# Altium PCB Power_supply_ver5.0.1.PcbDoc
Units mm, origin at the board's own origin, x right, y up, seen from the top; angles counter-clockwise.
Board outline 94.86 x 64.25 mm, 2 copper layers (Top Layer, Bottom Layer); 104 components, 45 nets, 301 pads, 37 vias.
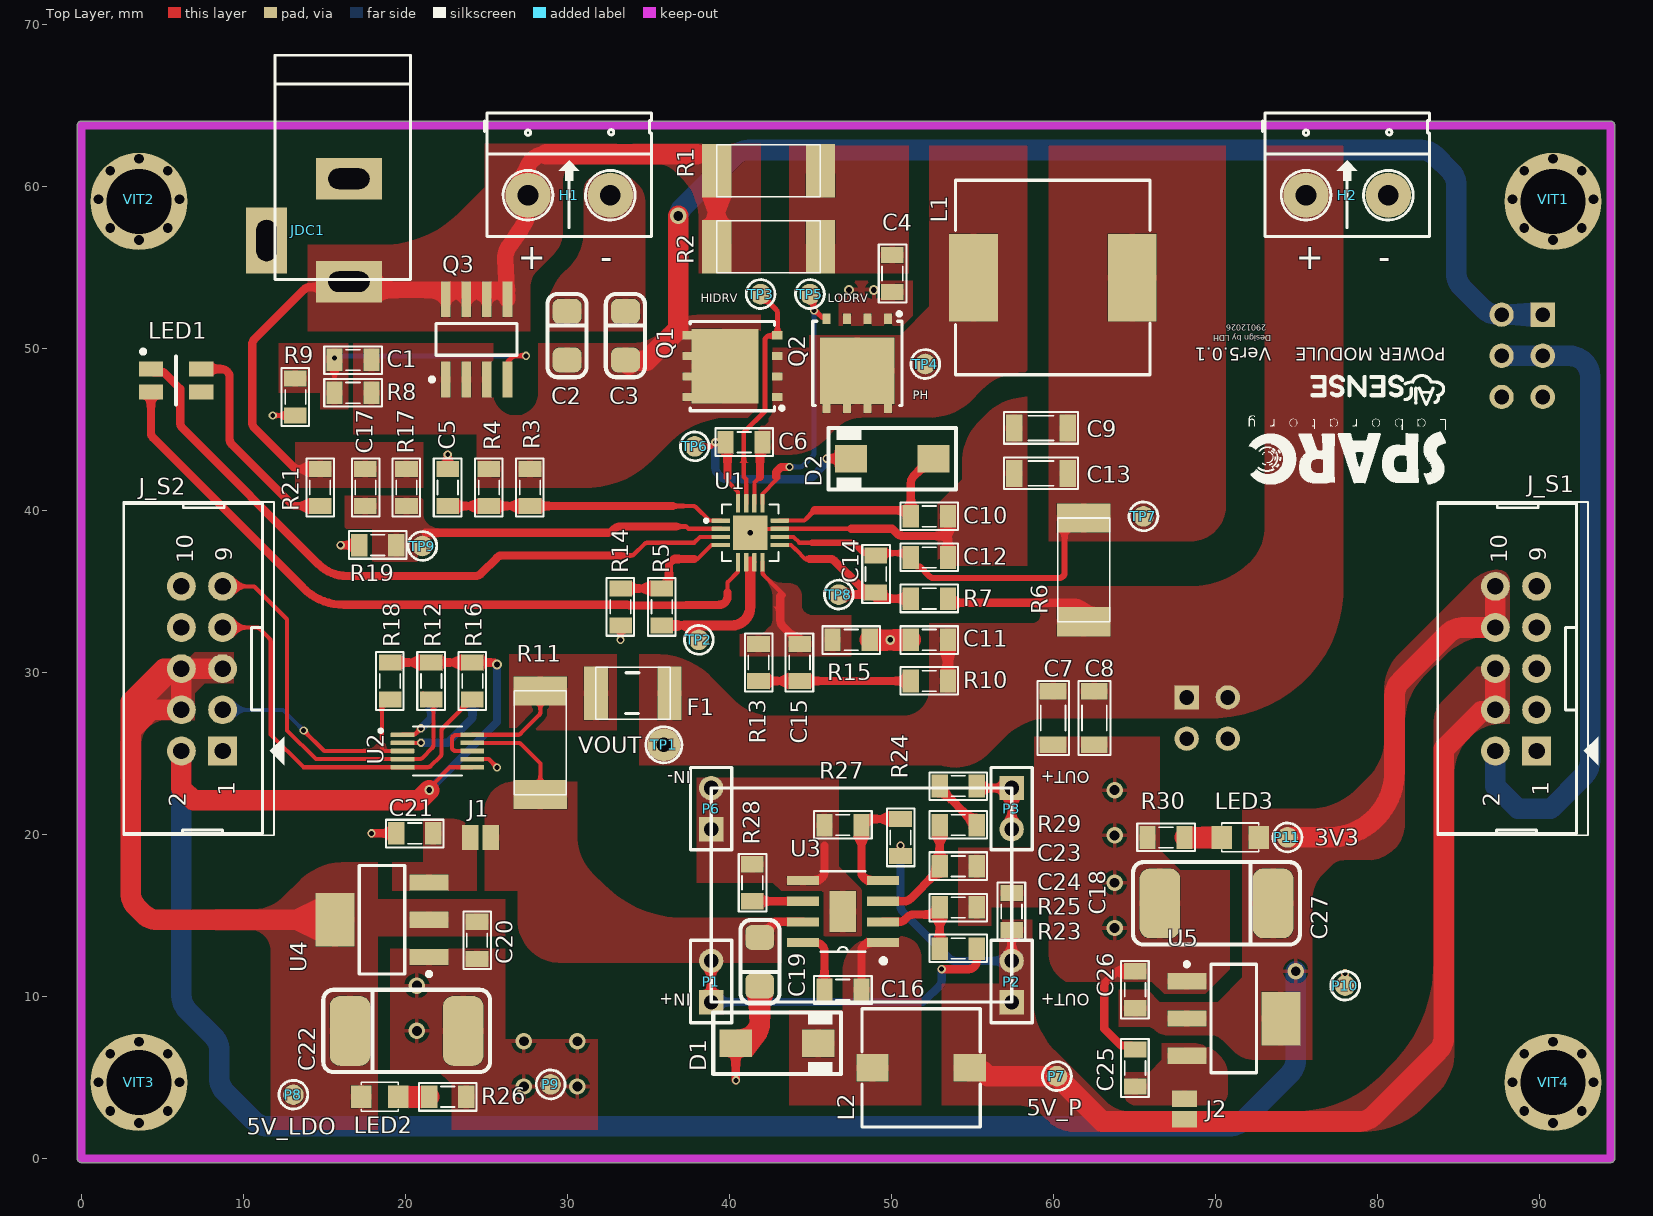
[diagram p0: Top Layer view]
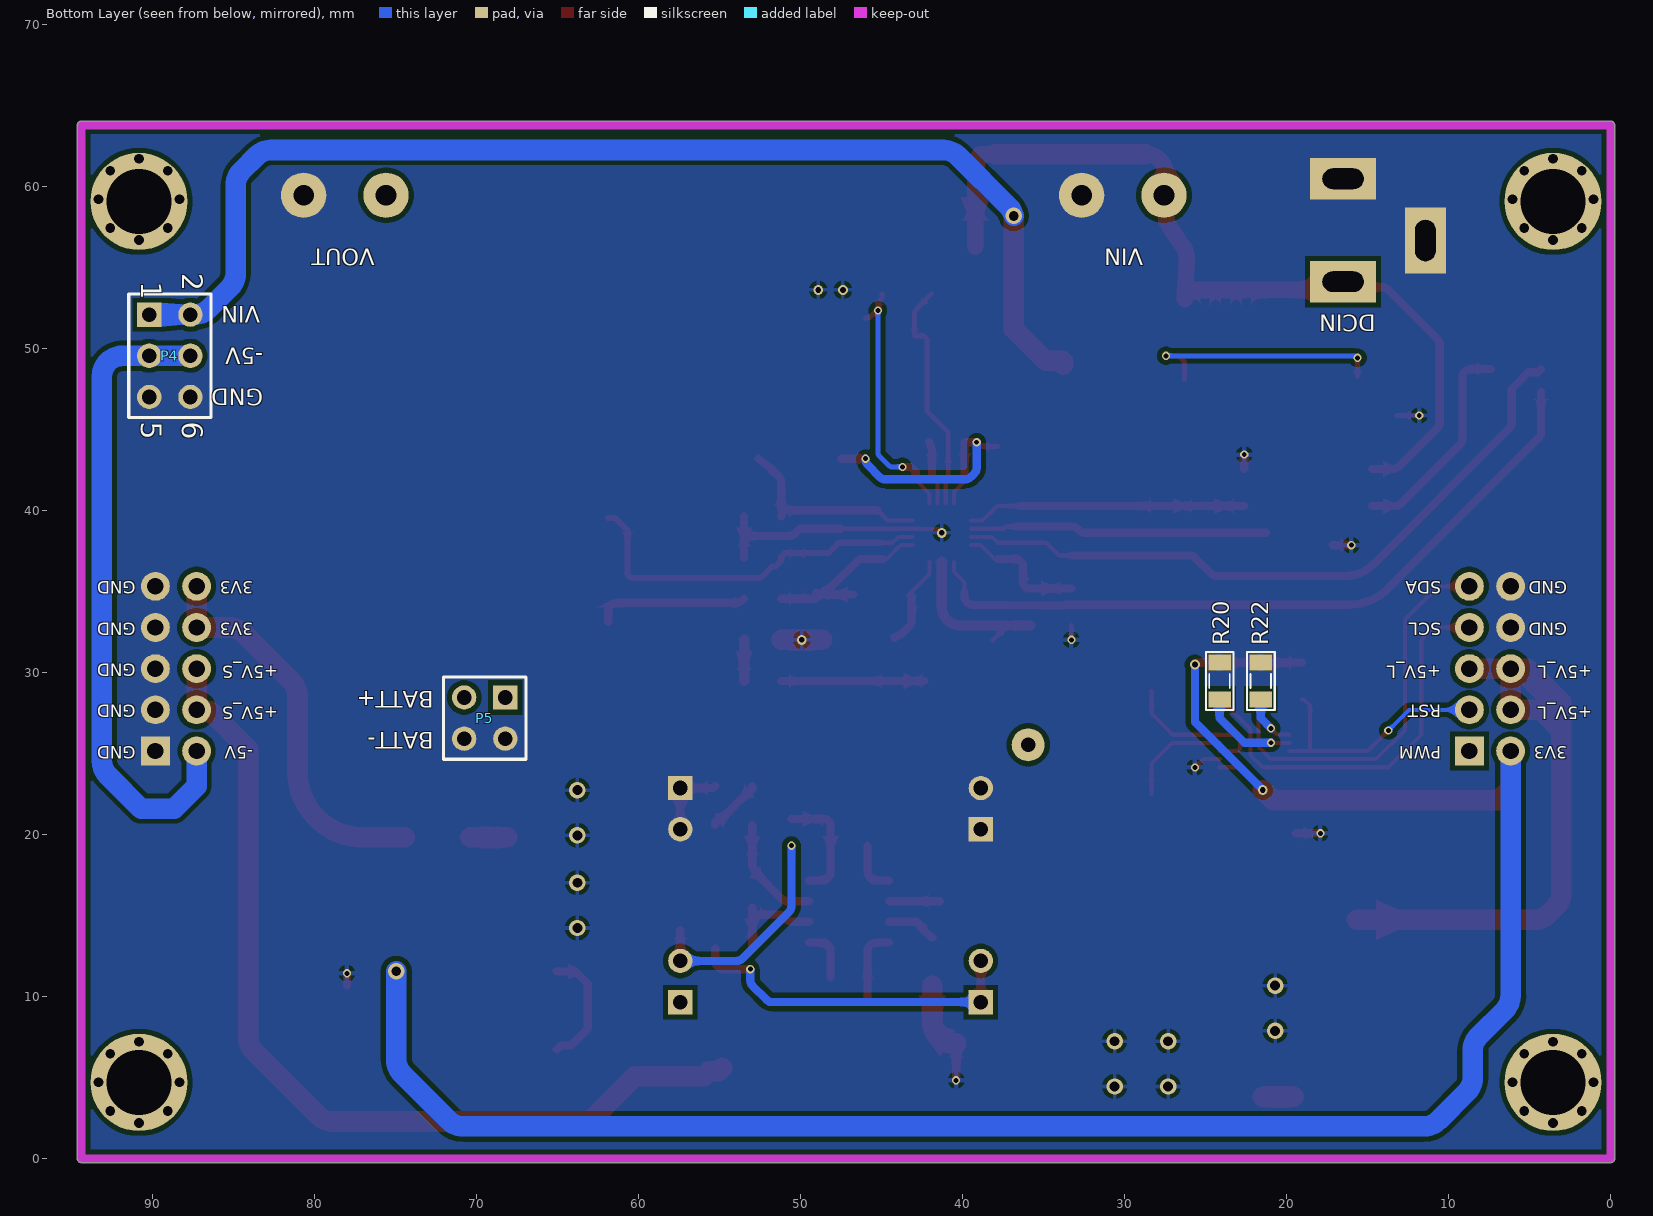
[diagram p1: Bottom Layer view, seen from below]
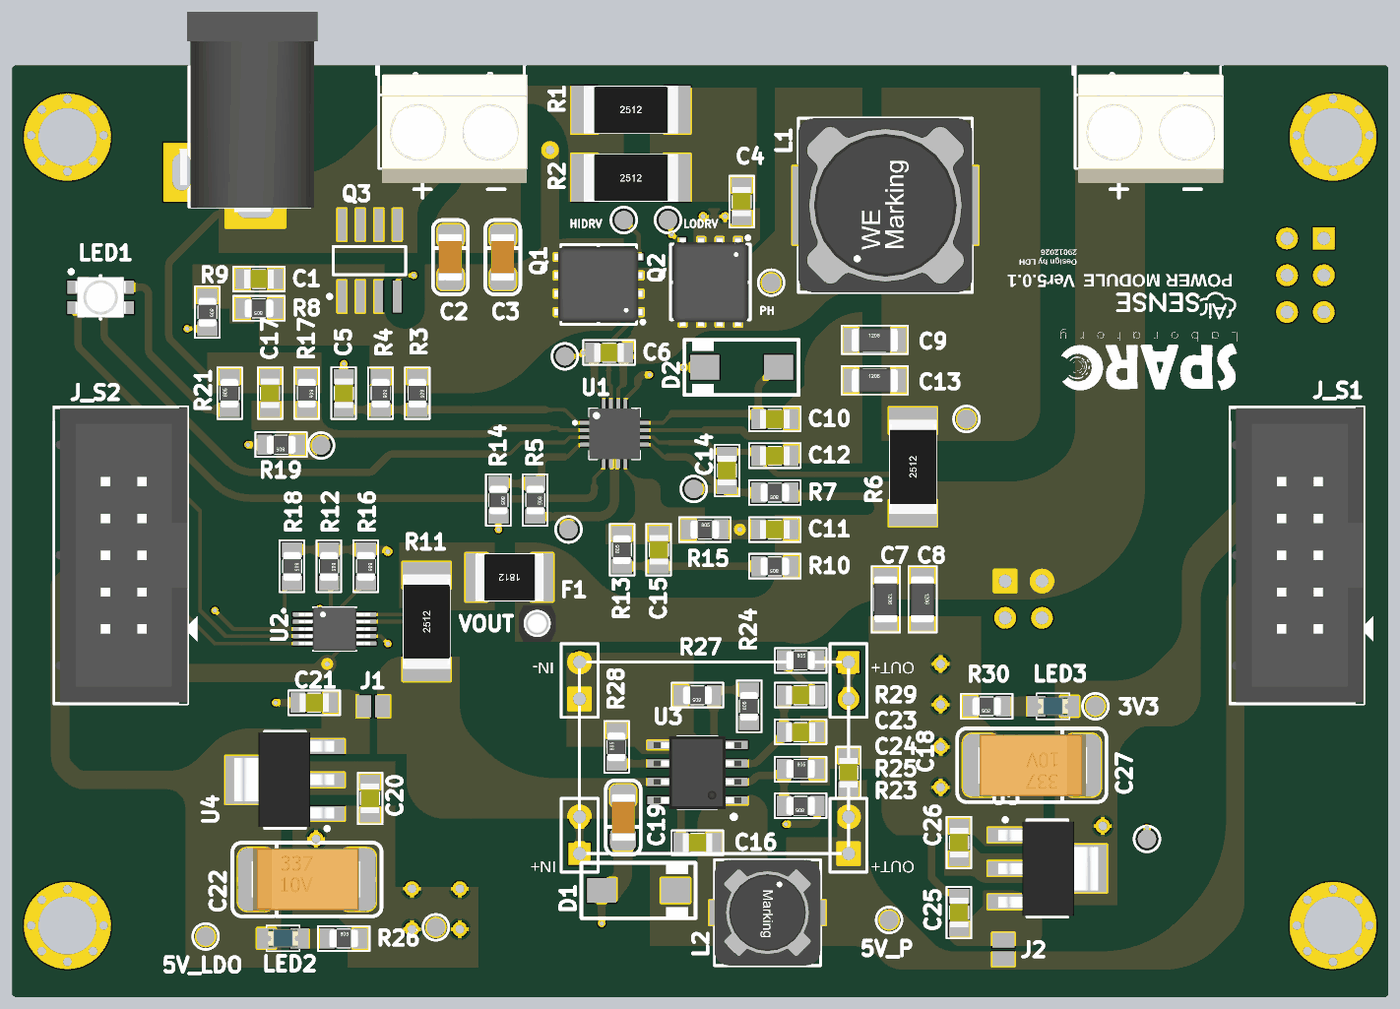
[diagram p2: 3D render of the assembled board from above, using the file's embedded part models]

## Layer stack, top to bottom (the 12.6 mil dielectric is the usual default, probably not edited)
Top Solder: solder mask 0.0102, Solder Resist, Dk 3.5
Top Layer: signal copper 0.0356
Dielectric 1: dielectric 0.32, FR-4, Dk 4.8
Bottom Layer: signal copper 0.0356
Bottom Solder: solder mask 0.0102, Solder Resist, Dk 3.5

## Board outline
0,-0.25 cw(c0,0) -0.25,0.002 -0.25,0.003 -0.25,63.754 cw(c0,63.754) 0,64.004 94.361,64.004 cw(c94.361,63.754) 94.611,63.754 94.611,0 cw(c94.361,0) 94.361,-0.25

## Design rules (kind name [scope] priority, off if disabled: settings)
Clearance [All] p1: gap=0.305 ignorepadtopadclearanceinfootprint=FALSE except(0: Arc-Text Track-Text SMDPad-Text THPad-Text Via-Text Fill-Text Poly-Text Region-Text Text-Text; 0.076: SMDPad-SMDPad SMDPad-THPad; 0.127: Arc-Hole Track-Hole SMDPad-Hole THPad-Hole Via-Hole Fill-Hole Poly-Hole Region-Hole Text-Hole; 0.203: Arc-Arc Arc-Track Arc-SMDPad Arc-Via Track-Track Track-SMDPad Track-Via SMDPad-Via THPad-Via Via-Via)
HoleSize HoleSize_1 [All] p1: absolutevalues=TRUE maxlimit=25.4 minlimit=0.025 maxpercent=80.000 minpercent=20.000
HoleToHoleClearance [All] p1: gap=0.025 allowstackedmicrovias=TRUE
MinimumSolderMaskSliver [All] p1: minsoldermaskwidth=0
PlaneClearance [All] p1: clearance=0.381
PolygonConnect [All] p1: thpad.connectstyle=Direct thpad.reliefconductorwidth=0.254 thpad.reliefentries=4 thpad.polygonreliefangle="90 Angle" thpad.airgapwidth=0.254 smdpad.connectstyle=Relief smdpad.reliefconductorwidth=0.381 smdpad.reliefentries=4 smdpad.polygonreliefangle="90 Angle" smdpad.airgapwidth=0 via.connectstyle=Relief via.reliefconductorwidth=0.305 via.reliefentries=4 via.polygonreliefangle="90 Angle" via.airgapwidth=0.254
RoutingPriority [InNet('No Net')] p1: routingpriority=0
RoutingVias [All] p1: holewidth=0.508 width=0.508 viastyle="Through Hole" minholewidth=0.305 minwidth=0.508 maxholewidth=0.711 maxwidth=1.27
SMDToPlane [All] p1: distance=0
SilkToSilkClearance [All] p1: silktosilkclearance=0
SilkToSolderMaskClearance [IsPad] p1: minsilkscreentomaskgap=0 clearancetoexposedcopper=TRUE
SolderMaskExpansion [All] p1: expansion=0.102 istentingtop=FALSE
SupplyNets "Schematic Supply Nets_6" [InNet('TERM_EN')] p1: voltage=0.000
SupplyNets "Schematic Supply Nets_5" [InNet('3V3')] p2: voltage=0.000
SupplyNets "Schematic Supply Nets_4" [InNet('GND')] p3: voltage=0.000
SupplyNets "Schematic Supply Nets_2" [InNet('5V_PS')] p4: voltage=0.000
SupplyNets "Schematic Supply Nets_1" [InNet('-5V')] p5: voltage=0.000
SupplyNets "Schematic Supply Nets" [InNet('5V_LDO')] p6: voltage=0.000
UnRoutedNet [All] p1: checkbadconnections=TRUE
Width [All] p1: maxlimit=1.27 minlimit=0.254 preferedwidth=0.508
22 further rules are at their usual default settings.

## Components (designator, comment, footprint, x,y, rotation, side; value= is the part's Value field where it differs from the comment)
C1 "0.1uF" CAP_0805 16.764,49.276 r0 top value=33p
C2 "10uF 3216" CAP_3216 29.921,50.724 r270 top value=33p
C3 "10uF 3216" CAP_3216 33.528,50.724 r270 top value=33p
C4 "2.2uF" CAP_0805 50.038,54.61 r90 top value=33p
C5 "0.1uF" CAP_0805 22.606,41.402 r270 top value=33p
C6 "1uF" CAP_0805 40.894,44.196 r180 top value=33p
C7 "4.7uF" CAP_1206 59.96,27.186 r270 top value=33p
C8 "1uF" CAP_1206 62.5,27.186 r270 top value=33p
C9 "10uF" CAP_1206 59.212,45.069 r0 top value=33p
C10 "10uF" CAP_0805 52.324,39.624 r180 top value=33p
C11 "0.1uF" CAP_0805 52.324,32.004 r0 top value=33p
C12 "10uF" CAP_0805 52.324,37.084 r180 top value=33p
C13 "10uF" CAP_1206 59.212,42.275 r0 top value=33p
C14 "10uF" CAP_0805 49.022,36.068 r90 top value=33p
C15 "0.1uF" CAP_0805 44.323,30.607 r270 top value=33p
C16 "100nF" CAP_0805 46.99,10.414 r0 top value=33p
C17 "22pF" CAP_0805 17.526,41.402 r90 top value=33p
C18 "22uF 6.3V" CAP_0805 57.404,15.24 r270 top value=33p
C19 "10uF 50V" CAP_3216 41.91,12.192 r90 top value=33p
C20 "0.1uF" CAP_0805 24.413,13.462 r90 top value=33p
C21 "0.1uF" CAP_0805 20.574,20.066 r0 top value=33p
C22 "100uF" CAP_7343 20.006,7.874 r0 top
C23 "220pF" CAP_0805 54.102,20.574 r180 top value=33p
C24 "100nF" CAP_0805 54.102,18.034 r180 top value=33p
C25 "100nF" CAP_0805 65.024,5.588 r270 top value=33p
C26 "100nF" CAP_0805 65.024,10.414 r270 top value=33p
C27 "100uF" CAP_7343 70.104,15.748 r180 top
D1 "SS34-HF" SMA 42.926,7.112 r0 top value="Diode c?m 1N5408"
D2 "1N5819" SMA 50.034,43.18 r180 top value="Diode c?m 1N5408"
F1 "F1A" RES-SMD-1812 34.29,28.702 r180 top value=Fuse
H1 "Header 2" HED2 27.559,59.436 r0 top
H2 "Header 2" HED2 75.565,59.436 r0 top
J1 "Jumper2" JUMPER2 24.003,19.812 r180 top
J2 "Jumper2" JUMPER2 68.072,3.683 r90 top
J_S1 "SOURCE" IDC10 87.249,30.226 r90 top locked value="Header 5x2"
J_S2 "SOURCE_SIG" IDC10 6.172,30.226 r90 top locked value="Header 5x2"
JDC1 "Jac DC" DC-IN 13.97,57.277 r270 top
L1 "10uH" L-SMD-M-12x10 59.944,54.356 r90 top value="150 mH"
L2 "22uH" L-SMD-M-7.3x4.5 51.816,5.588 r90 top value="150 mH"
LED1 "LED RGB SMD v1" "LED RGB 3528" 5.842,48.006 r0 top
LED2 "LED" LED-0805-Blue 17.272,3.81 r0 top value="LED 3 ly Single Colour"
LED3 "LED" LED-0805-Blue 72.644,19.812 r180 top value="LED 3 ly Single Colour"
P1 "Header 2" HDR1X2 38.862,9.652 r90 top
P2 "Header 2" HDR1X2 57.404,9.652 r90 top
P3 "Header 2" HDR1X2 57.404,22.86 r270 top
P4 "Header 3X2" HDR2X3 90.17,52.07 r270 bottom
P5 "Header 2X2" HDR2X2 68.199,28.448 r0 bottom
P6 "Header 2" HDR1X2 38.862,20.32 r90 top
P7 "5V_P" "Testpoint 50ml" 60.198,5.08 r0 top value="Test Point"
P8 "5V_LDO" "Testpoint 50ml" 13.081,3.937 r90 top value="Test Point"
P9 "GND" "Testpoint 50ml" 28.956,4.572 r0 top value="Test Point"
P10 "GND" "Testpoint 50ml" 77.978,10.668 r0 top value="Test Point"
P11 "3V3" "Testpoint 50ml" 74.422,19.812 r0 top value="Test Point"
Q1 "AON6508" MOSFET_HP_8Pin 40.176,48.895 r180 top
Q2 "AON6508" MOSFET_HP_8Pin 47.879,49.066 r270 top
Q3 "AO4407A" SOIC-8 24.384,50.546 r90 top
R1 "2R" RES-SMD-2512 42.402,60.825 r0 top
R2 "2R" RES-SMD-2512 42.402,56.126 r0 top
R3 "10R" RES-SMD-0805 27.686,41.402 r270 top
R4 "NC" RES-SMD-0805 25.146,41.402 r270 top
R5 "10k" RES-SMD-0805 35.814,34.036 r270 top
R6 "0.05" RES-SMD-2512 61.976,36.322 r90 top
R7 "0R" RES-SMD-0805 52.324,34.544 r180 top
R8 "10R" RES-SMD-0805 16.764,47.244 r180 top
R9 "10R" RES-SMD-0805 13.208,46.99 r270 top
R10 "0R" RES-SMD-0805 52.324,29.464 r180 top
R11 "0.05R" RES-SMD-2512 28.448,25.654 r90 top
R12 "10k" RES-SMD-0805 21.59,29.464 r270 top
R13 "499k" RES-SMD-0805 41.783,30.607 r90 top
R14 "10k" RES-SMD-0805 33.274,34.036 r270 top
R15 "100k" RES-SMD-0805 47.498,32.004 r0 top
R16 "10k" RES-SMD-0805 24.13,29.464 r270 top
R17 "499k" RES-SMD-0805 20.066,41.402 r270 top
R18 "10k" RES-SMD-0805 19.05,29.464 r270 top
R19 "36k" RES-SMD-0805 18.288,37.846 r180 top
R20 "10k" RES-SMD-0805 24.13,29.464 r90 bottom
R21 "1k" RES-SMD-0805 14.732,41.402 r90 top
R22 "10k" RES-SMD-0805 21.59,29.464 r90 bottom
R23 "100k" RES-SMD-0805 54.102,12.954 r180 top
R24 "249k" RES-SMD-0805 50.546,19.812 r90 top
R25 "24.9k" RES-SMD-0805 54.102,15.494 r0 top
R26 "220" RES-SMD-0805 22.606,3.81 r0 top
R27 "47k" RES-SMD-0805 46.99,20.574 r180 top
R28 "200k" RES-SMD-0805 41.402,17.018 r90 top
R29 "68.1k" RES-SMD-0805 54.102,22.987 r0 top
R30 "220" RES-SMD-0805 66.929,19.812 r180 top
TP1 "VOUT" TP1 35.941,25.527 r0 top value="Test Point"
TP2 "TP" "Testpoint 50ml" 38.1,32.004 r0 top value="Test Point"
TP3 "HIDRV" "Testpoint 50ml" 41.91,53.34 r90 top value="Test Point"
TP4 "PH" "Testpoint 50ml" 52.07,49.022 r90 top value="Test Point"
TP5 "LODRV" "Testpoint 50ml" 44.958,53.34 r90 top value="Test Point"
TP6 "TP" "Testpoint 50ml" 37.846,43.942 r90 top value="Test Point"
TP7 "TP" "Testpoint 50ml" 65.532,39.624 r90 top value="Test Point"
TP8 "TP" "Testpoint 50ml" 46.736,34.798 r90 top value="Test Point"
TP9 "TP" "Testpoint 50ml" 21.043,37.794 r90 top value="Test Point"
U1 "BQ24650" VQFN-16 41.275,38.608 r0 top
U2 "INA226" VSSOP-10 21.971,25.146 r0 top
U3 "MP1584" SOP8-PP 46.99,15.24 r180 top
U4 "LM1117" SOT-223 18.553,14.732 r90 top
U5 "LM1117" SOT-223 71.109,8.636 r270 top
VIT1 "1" "Screw Hole 4mm"#1 90.805,59.182 r0 top locked net-tie
VIT2 "1" "Screw Hole 4mm"#1 3.556,59.182 r0 top locked net-tie
VIT3 "1" "Screw Hole 4mm"#2 3.556,4.699 r0 top locked net-tie
VIT4 "1" "Screw Hole 4mm"#2 90.805,4.699 r0 top locked net-tie

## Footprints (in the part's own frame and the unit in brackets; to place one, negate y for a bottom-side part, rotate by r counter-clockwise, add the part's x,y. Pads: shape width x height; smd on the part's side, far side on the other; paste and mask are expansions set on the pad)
CAP_0805 [mil]
  rect 39.37x55 smd: 1(-45,0) 2(45,0)
  silkscreen extent -70,-34 70,33, body extent -40,-25 40,25, height 24
CAP_1206 [mil]
  rect 40x65 smd: 1(-65,0) 2(65,0)
  silkscreen extent -90,-38 90,39, body extent -63,-31 63,32, height 40
CAP_3216 [mil]
  rrect50% 60x70 smd: 1(-60.99,2) 2(56.99,2)
  silkscreen extent -103,-46 99,49, body extent -65,-30 61,32, height 39
CAP_7343 [mm] "Capacitor Tantalum 7343"
  rrect50% 2.5x4.3 smd: 1(-3.429,0) 2(3.556,0)
  silkscreen extent -5.08,-2.54 5.21,2.54, body extent -3.75,-2.14 3.75,2.16, height 2.8
DC-IN [mil] "Jac DC input"
  rect 100x160 hole 50 slot 100 at 90 deg: 1(125,100) 2(-125,100)
  rect 160x100 hole 50 slot 100 at 0 deg: 3(25,-100)
  silkscreen extent -425,-80 120,250, body extent -410,-105 134,269, height 434
HDR1X2 [mm] "Connector; Header; 2 Position"
  rect 1.5x1.5 hole 0.9: 1(0,0)
  round 1.5 hole 0.9: 2(2.54,0)
  silkscreen extent -1.27,-1.27 3.81,1.27, body extent -1.27,-1.27 3.81,1.27, height 7
HDR2X2 [mm] "Connector; Header; 2x2 Position"
  rect 1.5x1.5 hole 0.9: 1(0,0)
  round 1.5 hole 0.9: 2(0,2.54) 3(2.54,0) 4(2.54,2.54)
  silkscreen extent -1.27,-1.27 3.81,3.81, body extent -1.27,-1.27 3.81,3.81, height 7
HDR2X3 [mm] "Connector; Header; 3x2 Position"
  rect 1.5x1.5 hole 0.9: 1(0,0)
  round 1.5 hole 0.9: 2(0,2.54) 3(2.54,0) 4(2.54,2.54) 5(5.08,0) 6(5.08,2.54)
  silkscreen extent -1.27,-1.27 6.35,3.81, body extent -1.27,-1.27 6.35,3.81, height 7
HED2 [mil] "Header 2, 2 pin, hight 300mil, Pin to Pin 200, Colour Green"
  round 110 hole 50: 1(0,0) 2(200,0)
  silkscreen extent -106,-100 300,200, body extent -92,-140 302,155, height 394
IDC10 [mil]
  rect 70x70 hole 40: 1(-200,-100)
  round 70 hole 40: 2(-200,0) 3(-100,-100) 4(-100,0) 5(0,-100) 6(0,0) 7(100,-100) 8(100,0) 9(200,-100) 10(200,0)
  silkscreen extent -405,-250 405,141, body extent -400,-223 400,135, height 366
JUMPER2 [mil]
  rect 40x60 smd: 1(-50,0) 2(0,0)
L-SMD-M-7.3x4.5 [mm] "WE-PDA SMD Shielded Power Inductor, 7345"
  rect 1.7x2 smd: 1(0,3) 2(0,-3)
  silkscreen extent -3.65,-3.65 3.65,3.65, body extent -3.65,-3.65 3.65,3.65, height 4.05
L-SMD-M-12x10 [mm] "WE-PDA SMD Shielded Power Inductor, 1210"
  rect 5.4x3 smd: 1(0,4.9) 2(0,-4.9)
  silkscreen extent -6,-6 6,6, body extent -6,-6 6,6, height 9.7
"LED RGB 3528" [mm]
  rect 1.5x0.9 smd: 1(1.55,0.707) 2(1.55,-0.71) 3(-1.55,0.707) 4(-1.55,-0.707)
  silkscreen extent -2.15,-1.5 0.03,1.9, body extent -1.75,-1.4 1.75,1.4, height 1.87
LED-0805-Blue [mil]
  rect 50x55 smd: 1(0,0) 2(90,0)
  silkscreen extent 0,-35 90,35, body extent 5,-25 85,25, height 43
MOSFET_HP_8Pin [mm]
  rect 0.65x0.5 smd: 1(-2.75,1.905) 2(-2.75,0.635) 3(-2.75,-0.635) 4(-2.75,-1.905)
  rect 0.55x0.5 smd: 5(2.795,-1.905) 6(2.795,-0.635) 7(2.795,0.635) 8(2.795,1.905)
  rect 4.12x4.6 smd: 9(0.46,0)
  silkscreen extent -3.13,-2.75 2.6,2.75, body extent -3,-2.75 3.05,2.75, height 0.95
RES-SMD-0805 [mil]
  rect 39.37x55 smd: 1(-45,0) 2(45,0)
  silkscreen extent -70,-34 70,33, body extent -39,-25 39,25, height 31
RES-SMD-1812 [mm] "Chip Capacitor, Body 3.2x2.5mm, IPC Medium Density"
  rect 1.5x3.3 smd: 1(-1.996,0) 2(2.54,0)
  silkscreen extent -2.04,-1.6 2.54,1.6, body extent -2,-1.6 2.5,1.6, height 0.6
RES-SMD-2512 [mm] "Chip Capacitor, Body 3.2x2.5mm, IPC Medium Density"
  rect 1.8x3.3 smd: 1(-3.2,0.127) 2(3.2,0.127)
  silkscreen extent -3.2,-1.47 3.2,1.73, body extent -3.2,-1.47 3.2,1.73, height 0.6
"Screw Hole 4mm"#1 [mm]
  round 0.6 hole 0.6: 1(-2.5,0) 1(-1.768,-1.768) 1(-1.768,1.768) 1(0,-2.5) 1(0,2.5) 1(1.768,-1.768) 1(1.768,1.768) 1(2.5,0)
  round 6 hole 4: 1(0,-0.127)
"Screw Hole 4mm"#2 [mm]
  round 0.6 hole 0.6: 1(-2.5,0) 1(-1.768,-1.768) 1(-1.768,1.768) 1(0,-2.5) 1(0,2.5) 1(1.768,-1.768) 1(1.768,1.768) 1(2.5,0)
  round 6 hole 4: 1(0,0)
SMA [mm]
  rect 2x1.7 smd: 1(-2.544,0) 2(2.544,0)
  silkscreen extent -3.94,-1.9 3.94,1.91, body extent -2.87,-1.4 2.87,1.4, height 2.29
SOIC-8 [mm] "SOIC, 8-Leads, Body 5,0x4,0mm (max), Pitch 1,27mm, IPC Medium Density"
  rect 2.2x0.6 smd: 1(-2.475,1.905) 2(-2.475,0.635) 3(-2.475,-0.635) 4(-2.475,-1.905) 5(2.475,-1.905) 6(2.475,-0.635) 7(2.475,0.635) 8(2.475,1.905)
  silkscreen extent -2.6,-2.5 0.98,2.88, body extent -3.2,-2.5 3.2,2.5, height 1.75
SOP8-PP [mil]
  rect 78x22 smd: 1(-96.99,75.01) 2(-96.99,25.01) 3(-96.99,-24.99) 4(-96.99,-74.99) 5(97.01,-74.99) 6(97.01,-24.99) 7(97.01,25.01) 8(97.01,75.01)
  rect 64x100 smd: 9(0,0)
  silkscreen extent -100,-98 54,121, body extent -119,-99 119,99, height 63
SOT-223 [mm] "SOT223, 4-Leads, Body 6.5x3.5mm, Pitch 2.3mm, Lead Span 7mm, IPC Medium Density"
  rect 1x2.4 smd: 1(-2.3,-2.9) 2(0,-2.9) 3(2.3,-2.9)
  rect 3.3x2.4 smd: 2(0,2.9)
  silkscreen extent -3.47,-3.03 3.35,1.4, body extent -3.23,-3.39 3.27,3.5, height 1.72
"Testpoint 50ml" [mm]
  round 1.27 smd: 1(0,0)
  silkscreen extent -0.89,-0.89 0.89,0.89
TP1 [mil] "Test point"
  round 80 hole 35: 1(0,0)
  silkscreen extent -44,-44 44,44, body extent -50,-50 50,50, height 178
VQFN-16 [mm]
  rrect25% 1.143x0.26 smd: 1(-1.812,0.75) 2(-1.812,0.25) 3(-1.812,-0.25) 4(-1.812,-0.75) 9(1.812,-0.75) 10(1.812,-0.25) 11(1.812,0.25) 12(1.812,0.75)
  rrect25% 0.26x1.143 smd: 5(-0.75,-1.812) 6(-0.25,-1.812) 7(0.25,-1.812) 8(0.75,-1.812) 13(0.75,1.812) 14(0.25,1.812) 15(-0.25,1.812) 16(-0.75,1.812)
  rect 2.14x2.14 smd paste-0.39: 17(0,0)
  silkscreen extent -2.82,-1.75 1.75,1.75, body extent -1.75,-1.75 1.75,1.75, height 1
VSSOP-10 [mm]
  rrect25% 1.47x0.28 smd: 1(-2.15,1) 2(-2.15,0.5) 3(-2.15,0) 4(-2.15,-0.5) 5(-2.15,-1) 6(2.15,-1) 7(2.15,-0.5) 8(2.15,0) 9(2.15,0.5) 10(2.15,1)
  silkscreen extent -3.6,-1.5 1.5,1.5, body extent -2.46,-1.5 2.46,1.5, height 1.1

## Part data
C1 C2 C3 C4 C5 C6 C7 C8 C9 C10 C11 C12 C13 C14 C15 C17: library part CapSMD, "Capacitor"
C16 C18 C20 C21 C23 C24 C25 C26: library part CapSMD, "C 0805"
C19: library part CapSMD, "C 1206"
C22 C27: library part CAP_TAN_SMD, "C Tan 7343"
D1 D2: library part 1N5822, "Schottky Rectifiers"
F1: library part Fuse, "Fuse 5A"
H1 H2: library part Hed2, "Header 2 (Green)"
J1 J2: "Jumper, 2-Pin"
J_S1 J_S2: library part "IDC 5X2"
JDC1: library part DCIN, "Jac DC input"
L1: library part Inductor, "Inductor"
L2: library part Inductor, "6.8-10uH"
LED2 LED3: "LED Single colour Green and Red"
P1 P2 P3 P6: "Header, 2-Pin"
P4: "Header, 3-Pin, Dual row"
P5: "Header, 2-Pin, Dual row"
P7 P8 P9 P10 P11 TP2 TP3 TP4 TP5 TP6 TP7 TP8 TP9: library part TP_1, "Test Point"
Q1 Q2: library part MOSFET-N, "MFET-CHP"
Q3: library part MOSFET-P, "MFET-ChP"
R1 R2 R6: library part "Resistor - SMD", "Resistor - SMD 2512", Manufacturer="Generic Components"
R3 R4 R5 R7 R10 R13 R14 R15 R17 R19 R21: library part "Resistor - SMD", "Resistor - SMD 0805", Manufacturer="Generic Components"
R8 R9 R12 R16 R18 R20 R22 R23 R26 R28 R29 R30: library part "Resistor - SMD", "R 0805", Manufacturer="Generic Components"
R11: library part "Resistor - SMD", "R 2512 1%", Manufacturer="Generic Components"
R24 R25 R27: library part "Resistor - SMD", "R 0805 1%", Manufacturer="Generic Components"
TP1: library part TP1, "Test Point"
U1: "BQ24650 Stand-Alone Synchronous Buck Battery Charge Controller for Solar Power / With Maximum Power Point Tracking"
U2: "Current Sensing IC"
U3: "MP1584, The wide 4.5V to 28V input range accommodates a   variety   of   step-down   applications, SOIC8E"
U4 U5: "3V3 5V LDO, AMS1117, LDI1117"
VIT1 VIT2 VIT3 VIT4: library part VIT, "Oc Vit"

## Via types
v1: diameter 0.508, hole 0.305, Top Layer to Bottom Layer, 19 vias
v2: diameter 1.016, hole 0.61, Top Layer to Bottom Layer, 12 vias
v3: diameter 0.61, hole 0.356, Top Layer to Bottom Layer, 6 vias

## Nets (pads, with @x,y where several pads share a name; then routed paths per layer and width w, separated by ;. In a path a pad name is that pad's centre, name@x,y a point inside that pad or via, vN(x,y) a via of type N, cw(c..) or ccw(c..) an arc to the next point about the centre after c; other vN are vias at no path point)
3V3: C26.2 C27.1 J_S1.8 J_S1.10 J_S2.2 LED3.1 P11.1 R12.1 R16.1 R18.1 U2.6 U5.2 | length 158.2
  Top Layer w0.254: v3(21.463,22.733) 21.463,22.829 21.63,22.997 21.63,23.027 22.749,24.146 U2.6
  Top Layer w0.508: R18.1 25.499,30.607 25.627,30.48 v3(25.654,30.48)
  Top Layer w1.27: J_S2.2 6.172,22.842 6.916,22.098 20.828,22.098 v3(21.463,22.733) ; P11.1 76.962,19.812 ccw(c76.962,23.876) 81.026,23.876 81.026,28.557 cw(c82.296,28.557) 81.398,29.455 84.338,32.395 cw(c85.235,31.496) 85.235,32.766 J_S1.8 J_S1.10
  Bottom Layer w0.508: v3(21.463,22.733) 25.654,26.924 v3(25.654,30.48)
  Bottom Layer w1.27: J_S2.2 6.172,10.051 ccw(c7.442,10.051) 6.538,9.159 ccw(c7.442,10.051) 6.542,9.155 8.139,7.558 cw(c7.239,6.662) 8.509,6.662 8.509,4.996 ccw(c9.779,4.996) 8.88,4.1 10.628,2.352 ccw(c11.524,3.251) 11.524,1.981 70.797,1.981 ccw(c70.797,3.251) 71.694,2.352 74.559,5.217 ccw(c73.66,6.114) 74.93,6.114 v2(74.93,11.557)
5V_LDO: C20.2 C22.1 J_S2.4 J_S2.5 J_S2.6 LED2.1 P8.1 U4.2 | length 43.5
  Top Layer w0.508: 3.589,26.957 3.589,27.643 J_S2.6 5.932,29.986 5.094,29.986
  Top Layer w1.27: J_S2.5 J_S2.6 ; U4.2@15.653,14.732 4.717,14.732 cw(c4.717,16.002) 3.82,15.103 3.419,15.504 cw(c4.318,16.401) 3.048,16.401 3.048,26.412 cw(c4.318,26.41) 3.048,26.416 ; 3.048,26.416 3.048,28.18 5.094,30.226 J_S2.6 ; 3.048,26.416 3.589,26.957 4.318,27.686 J_S2.4 J_S2.6
5V_PS: C18.2 J2.1 J_S1.4 J_S1.6 L2.2 P2.1 P2.2 P7.1 R24.1 | length 71.7
  Top Layer w0.508: R24.1 v1(50.546,19.304) ; P2.2 C18.2
  Top Layer w1.27: L2.2 55.031,5.373 55.632,5.373 55.925,5.08 P7.1 ; P7.1@60.462,4.816 62.992,2.286 68.072,2.286 78.849,2.286 ccw(c78.849,3.556) 79.746,2.657 83.703,6.614 ccw(c82.804,7.511) 84.074,7.511 84.074,10.423 84.074,25.273 86.39,27.589 87.152,27.589 J_S1.4 J_S1.6
  Bottom Layer w0.508: v1(50.546,19.304) 50.546,15.577 ccw(c51.054,15.577) 50.648,15.273 ccw(c51.054,15.577) 50.694,15.219 53.573,12.34 ccw(c53.931,12.7) 53.627,12.294 ccw(c53.931,12.7) 53.931,12.192 P2.2
-5V: J_S1.2 P4.3 P4.4 | length 40
  Bottom Layer w1.27: J_S1.2 87.249,22.987 88.646,21.59 90.678,21.59 92.719,23.631 ccw(c91.821,24.529) 93.091,24.529 93.091,48.26 ccw(c91.821,48.26) 91.821,49.53 P4.4
BTST: C6.2 D2.2 TP6.1 U1.16 | length 17.1
  Top Layer w0.254: 39.872,42.053 39.872,41.789 40.525,41.136 U1.16
  Top Layer w0.305: TP6.1 38.844,43.942 39.098,44.196 v1(39.116,44.196)
  Top Layer w0.508: v1(39.116,44.196) C6.2@39.832,44.196 ; 39.872,42.053 C6.2@39.872,44.196 ; v1(45.974,43.18) D2.2
  Bottom Layer w0.508: v1(39.116,44.196) 39.116,42.628 ccw(c39.624,42.628) 39.264,42.27 39.476,42.058 ccw(c39.834,42.418) 39.834,41.91 44.748,41.91 ccw(c44.748,42.418) 45.052,42.012 ccw(c44.748,42.418) 45.106,42.058 45.826,42.778 ccw(c45.466,43.136) 45.974,43.136 v1(45.974,43.18)
GND: C2.1 C3.1 C4.1 C5.1 C7.2 C8.2 C9.1 C10.1 C11.1 C12.1 C13.1 C18.1 C19.1 C20.1 C21.1 C22.2 C24.1 C25.1 C26.1 C27.2 D1.1 H1.2 H2.2 J_S1.1 J_S1.3 J_S1.5 J_S1.7 J_S1.9 J_S2.8 J_S2.10 JDC1.2 JDC1.3 P3.1 P3.2 P4.5 P4.6 P5.2 P5.4 P6.1 P6.2 P9.1 P10.1 Q2.1 Q2.2 Q2.3 R9.2 R14.2 R15.2 R19.2 R20.2 R22.2 R25.2 R26.2 R27.2 R28.2 R29.2 R30.2 U1.11 U1.17 U2.7 U3.5 U3.9 U4.1 U5.1 | length 48.1
  Top Layer w0.254: U2.7 25.138,24.646 v1(25.654,24.13) ; v3(41.275,38.608) 41.518,38.851 42.639,38.851 42.646,38.858 U1.11 47.494,38.858 47.498,38.862
  Top Layer w0.305: v1(11.811,45.847) R9.2 ; v1(33.274,32.004) R14.2
  Top Layer w0.508: v1(16.002,37.846) R19.2 ; v1(17.907,20.066) C21.1 ; C5.1 v1(22.606,43.434) ; D1.1 40.382,4.83 v1(40.386,4.826) ; U3.5 45.263,17.17 45.339,17.17 ccw(c45.339,17.678) 45.847,17.678 45.847,19.304 ; 47.498,38.862 50.026,38.862 50.322,38.566 50.323,38.565 ccw(c50.681,38.926) 50.376,38.519 ccw(c50.681,38.925) 50.681,38.417 53.467,38.417 ; C12.1 53.467,38.417 ; C10.1 53.467,38.417 ; R29.2 55.372,22.86 P3.1 P3.2 ; C25.1 64.778,6.977 64.143,6.977 63.119,8.001 63.119,10.795 63.861,11.537 65.004,11.537 C26.1 ; P10.1 v1(77.978,11.43)
  Top Layer w1.27: D1.1 40.747,7.122 ccw(c40.589,8.382) 41.859,8.382 C19.1 ; R15.2 C11.1
  other v2: 27.305,4.445 30.607,4.445 27.305,7.239 30.607,7.239 20.701,7.874 20.701,10.668 63.754,14.224 63.754,17.018 63.754,19.939 63.754,22.733
  other v3: 49.911,32.004 47.371,53.594 48.895,53.594
HIDRV: Q1.4 TP3.1 U1.15 | length 14.6
  Top Layer w0.254: 40.872,42.053 41.025,41.9 U1.15
  Top Layer w0.305: 40.872,42.053 40.872,44.805 42.182,46.115 42.182,50.575 42.361,50.753 42.954,50.753 42.954,52.17 ccw(c42.649,52.17) 42.865,52.385 TP3.1
I2CSW_SCL: J_S2.7 R16.2 U2.5 | length 25.1
  Top Layer w0.254: J_S2.7 10.817,32.766 cw(c10.817,32.512) 10.969,32.715 cw(c10.817,32.512) 10.996,32.692 11.61,32.078 cw(c11.43,31.899) 11.633,32.051 cw(c11.43,31.899) 11.684,31.899 11.684,26.162 13.7,24.146 U2.5 21.374,24.146 ccw(c21.374,24.4) 21.526,24.197 ccw(c21.374,24.4) 21.553,24.22 22.151,24.818 ccw(c21.971,24.997) 22.174,24.845 ccw(c21.971,24.997) 22.225,24.997 22.225,26.382 cw(c22.479,26.382) 22.276,26.535 cw(c22.479,26.382) 22.299,26.561 24.059,28.321 R16.2@24.257,28.321
I2CSW_SDA: J_S2.9 R12.2 U2.4 | length 25.3
  Top Layer w0.254: J_S2.9 10.668,35.306 12.7,33.274 12.7,26.416 14.47,24.646 U2.4 20.858,24.646 ccw(c20.858,24.9) 21.037,24.72 21.643,25.326 ccw(c21.463,25.505) 21.666,25.353 ccw(c21.463,25.505) 21.717,25.505 R12.2@21.717,28.321
  Top Layer w0.381: R12.2@21.082,28.631 21.392,28.321 R12.2
LODRV: Q2.4 TP5.1 U1.13 | length 16
  Top Layer w0.254: U1.13 42.028,40.423 42.028,41.012 42.872,41.856 42.872,42.053
  Top Layer w0.305: TP5.1 44.958,53.079 45.173,52.864 45.173,52.363 v1(45.212,52.324) 45.287,52.324 45.72,51.891 45.899,51.891 Q2.4
  Top Layer w0.508: 42.872,42.053 42.872,42.351 43.183,42.662 43.481,42.662 43.491,42.672 v1(43.688,42.672)
  Bottom Layer w0.305: v1(43.688,42.672) 44.324,42.672 ccw(c44.324,42.977) 44.539,42.761 45.123,43.345 ccw(c44.907,43.56) 45.151,43.377 ccw(c44.907,43.56) 45.212,43.56 v1(45.212,52.324)
MPPSET: C17.1 R17.2 R19.1 TP9.1 U1.2 | length 18.4
  Top Layer w0.254: 36.703,38.997 37.33,38.997 37.469,38.858 U1.2
  Top Layer w0.508: 21.243,38.608 32.429,38.608 ccw(c32.429,39.116) 32.787,38.756 32.88,38.849 cw(c33.238,38.489) 33.238,38.997 36.703,38.997
NetC1_1: C1.1 Q3.4 R8.2 R9.1 | length 15.3
  Top Layer w0.305: 15.621,48.26 v1(15.621,49.403) ; Q3.4 26.289,49.023 cw(c26.594,49.023) 26.378,49.238 26.581,49.441 cw(c26.796,49.225) 26.796,49.53 v1(27.432,49.53)
  Bottom Layer w0.305: v1(15.621,49.403) 15.659,49.441 cw(c15.874,49.225) 15.874,49.53 v1(27.432,49.53)
NetC4_2: C4.2 R1.2 R2.2
NetC5_2: C5.2 R3.2 R4.2 U1.1 | length 17.2
  Top Layer w0.254: 36.484,40.259 37.741,40.259 cw(c37.741,40.005) 37.92,40.185 38.747,39.358 U1.1
  Top Layer w0.508: C5.2 R4.2 ; R4.2@25.209,40.281 25.59,40.262 25.642,40.26 ccw(c25.666,40.767) 25.666,40.259 R3.2 36.484,40.259
NetC10_2: C10.2 D2.1 U1.12 | length 12.2
  Top Layer w0.254: U1.12 44.607,39.358 45.246,39.997
  Top Layer w0.508: 45.246,39.997 45.563,39.997 C10.2@50.808,39.997 ; C10.2@51.008,39.992 C10.2 ; C10.2@51.181,39.997 51.181,41.67 cw(c51.816,41.67) 51.366,42.118 51.895,42.647 D2.1
NetC15_1: C15.1 R13.2 R15.1 U1.8 | length 5.6
  Top Layer w0.254: U1.8 42.028,36.351 42.029,36.179 ccw(c42.283,36.181) 42.103,36.002 43.351,34.754
  Top Layer w0.508: 43.126,34.687 43.126,33.213 ccw(c43.634,33.213) 43.274,32.854 43.752,32.377 C15.1@44.196,32.131
NetC15_2: C15.2 R10.2 R13.1 | length 8.8
  Top Layer w0.508: R13.1@42.336,29.464 R10.2
NetC16_1: C16.1 U3.8 | length 4.5
  Top Layer w0.508: U3.8 45.263,13.309 45.356,13.306 cw(c45.339,12.798) 45.847,12.798 C16.1@45.847,9.919
NetC16_2: C16.2 D1.2 L2.1 U3.1 | length 3.2
  Top Layer w0.508: 48.133,11.176 48.133,12.801 cw(c48.641,12.801) 48.641,13.309 48.717,13.309 U3.1
NetC21_2: C21.2 J1.2 U4.3
NetC23_1: C23.1 R29.1 | length 3.5
  Top Layer w0.508: R29.1 52.959,22.789 53.205,22.543 53.277,22.543 54.801,21.018 54.999,21.018 55.245,20.772 C23.1
NetC23_2: C23.2 C24.2 U3.3 | length 7
  Top Layer w0.508: U3.3 50.788,15.875 ccw(c50.788,16.383) 51.146,16.023 52.713,17.59 C24.2 C23.2
NetC25_2: C25.2 J2.2 U5.3
NetLED1_1: LED1.1 R21.1 | length 13.2
  Top Layer w0.508: LED1.1 8.636,48.713 cw(c8.636,48.205) 9.144,48.205 9.144,44.405 ccw(c9.652,44.406) 9.292,44.048 12.933,40.407 ccw(c13.291,40.767) 13.291,40.259 R21.1
NetLED1_3: LED1.3 U1.3 | length 42.6
  Top Layer w0.254: 33.274,37.211 33.931,37.211 ccw(c33.931,37.465) 34.083,37.262 ccw(c33.931,37.465) 34.11,37.285 34.748,37.923 cw(c34.927,37.743) 34.775,37.946 cw(c34.927,37.743) 34.927,37.997 37.816,37.997 38.177,38.358 U1.3
  Top Layer w0.508: LED1.3 4.488,48.517 5.077,48.517 6.096,47.498 6.096,45.421 ccw(c6.604,45.422) 6.244,45.064 14.647,36.661 ccw(c16.383,38.394) 16.383,35.941 24.301,35.941 ccw(c24.301,36.449) 24.605,36.043 ccw(c24.301,36.449) 24.66,36.09 25.632,37.062 cw(c25.991,36.703) 25.991,37.211 33.274,37.211
NetLED1_4: LED1.4 U1.5 | length 45.1
  Top Layer w0.254: 39.872,34.941 39.872,35.554 40.522,36.204 40.522,36.793 U1.5
  Top Layer w0.508: LED1.4 4.292,44.813 ccw(c4.8,44.813) 4.394,44.509 ccw(c4.8,44.813) 4.44,44.455 13.665,35.23 ccw(c16.188,37.68) 16.191,34.163 33.683,34.163 cw(c33.681,33.655) 33.817,34.144 ccw(c33.969,34.682) 33.969,34.123 35.119,34.123 ccw(c35.119,34.682) 35.124,34.123 39.363,34.163 ccw(c39.359,34.671) 39.866,34.66 39.872,34.941
NetLED2_2: LED2.2 R26.1 | length 1.9
  Top Layer w1.27: LED2.2 R26.1
NetLED3_2: LED3.2 R30.1 | length 2.3
  Top Layer w1.27: R30.1 LED3.2
NetR5_1: R5.1 R14.1 U1.4 | length 7.8
  Top Layer w0.254: 37.816,36.997 38.013,36.997 38.871,37.855 39.46,37.855 U1.4
  Top Layer w0.508: R14.1 R5.1 ; R5.1@36.012,35.179 36.258,35.425 36.258,36.699 36.556,36.997 37.816,36.997
NetR20_1: R20.1 U2.2 | length 6.1
  Top Layer w0.254: U2.2 20.947,25.646 v1(20.955,25.654)
  Bottom Layer w0.508: v1(20.955,25.654) 22.606,25.654 24.13,27.178 R20.1
NetR22_1: R22.1 U2.1 | length 3.3
  Top Layer w0.254: U2.1 19.834,26.159 20.571,26.159 v1(20.955,26.543)
  Bottom Layer w0.508: v1(20.955,26.543) 21.59,27.178 R22.1
NetR23_2: R23.2 R25.1 U3.2 | length 5.9
  Top Layer w0.508: U3.2 50.462,14.605 ccw(c50.462,15.113) 50.821,14.753 50.97,14.902 cw(c51.328,14.541) 51.328,15.05 R25.1@52.713,15.05 ; R23.2 52.959,15.05 R25.1
NetR24_2: R24.2 R27.1 U3.4 | length 7.2
  Top Layer w0.508: U3.4 48.717,17.17 48.641,17.17 cw(c48.641,17.678) 48.133,17.678 R27.1 48.133,20.709 48.379,20.955 R24.2
NetR28_1: R28.1 U3.6 | length 3.1
  Top Layer w0.508: R28.1 U3.6
PH: C6.1 L1.1 Q1.1 Q1.2 Q1.3 Q2.5 Q2.6 Q2.7 Q2.8 Q2.9 TP4.1 U1.14 | length 3.9
  Top Layer w0.254: U1.14 41.525,41.706 41.872,42.053
  Top Layer w0.508: 41.872,42.053 41.872,43.752 C6.1
SRN: C14.1 R7.2 TP8.1 U1.9 | length 11.7
  Top Layer w0.254: U1.9 43.09,37.855 43.794,37.855 44.11,37.54 44.121,37.54 44.664,36.997 44.928,36.997
  Top Layer w0.508: 44.928,36.997 46.146,36.997 cw(c46.146,36.489) 46.451,36.895 cw(c46.146,36.489) 46.506,36.848 48.04,35.314 48.484,35.068 48.73,34.822 48.86,34.692 ccw(c49.219,35.052) 49.219,34.544 R7.2 ; TP8.1 48.895,34.798 C14.1
SRP: C9.2 C12.2 C13.2 C14.2 L1.2 R6.2 TP7.1 U1.10 | length 23
  Top Layer w0.254: U1.10 43.938,38.358 44.299,37.997 45.085,37.997
  Top Layer w0.381: 45.085,37.997 47.485,37.997 cw(c47.485,37.616) 47.754,37.885 47.976,37.663 48.286,37.354 50.935,37.354 51.181,37.108 C12.2 51.181,36.886 51.529,36.538 51.727,36.538 52.362,35.903 ccw(c52.577,36.119) 52.577,35.814 60.326,35.814 ccw(c60.326,36.119) 60.541,35.903 60.582,35.944 ccw(c60.366,36.159) 60.67,36.159 60.67,38.775 61.418,39.522 R6.2
TERM_EN: R5.2 TP2.1 U1.6 U1.7 | length 10.7
  Top Layer w0.254: U1.6 U1.7
  Top Layer w0.305: 36.83,32.893 37.211,32.893 TP2.1
  Top Layer w0.635: R5.2 36.83,32.893 ; 37.211,32.893 40.129,32.893 40.13,32.893 ccw(c40.13,34.038) 41.275,34.037 41.275,36.83
V_IN: C17.2 H1.1 JDC1.1 Q3.5 Q3.6 Q3.7 Q3.8 R1.1 R2.1 R17.1 R21.2 | length 53.8
  Top Layer w0.508: R21.2 13.418,42.545 cw(c13.418,43.053) 13.06,42.693 10.689,45.064 cw(c11.049,45.422) 10.643,45.118 cw(c11.049,45.422) 10.541,45.422 10.541,50.209 cw(c11.049,50.209) 10.643,50.513 cw(c11.049,50.209) 10.689,50.567 13.739,53.617 cw(c14.097,53.257) 14.097,53.765 16.173,53.765 JDC1.1
  Top Layer w1.016: JDC1.1 17.907,53.594 Q3.5@26.289,53.594 ; Q3.5 26.26,53.593 26.164,55.506 cw(c27.433,55.568) 26.393,56.297 27.067,57.259 27.432,57.874 27.432,60.706 cw(c28.702,60.706) 28.702,61.976 ; 37.954,61.976 cw(c37.954,60.706) 37.966,61.976 38.937,61.967 R1.1 R2.1
  Top Layer w1.27: 28.702,61.976 37.954,61.976
V_IN_MOS: C1.2 C2.2 C3.2 P4.1 P4.2 Q1.5 Q1.6 Q1.7 Q1.8 Q1.9 Q3.1 Q3.2 Q3.3 R3.1 R4.1 R8.1 | length 74.2
  Top Layer w0.508: C3.2@33.579,49.098 C3.2@33.769,48.908
  Top Layer w1.27: C3.2@33.769,48.971 33.769,49.162 33.833,49.225 34.874,49.225 36.83,51.181 v2(36.83,58.166)
  Bottom Layer w1.27: v2(36.83,58.166) cw(c38.061,57.855) 37.162,58.752 40.268,61.858 cw(c41.166,60.96) 41.166,62.23 82.659,62.23 cw(c82.659,60.96) 83.556,61.859 84.465,60.95 cw(c83.566,60.053) 84.836,60.053 84.836,54.626 ccw(c86.106,54.628) 85.206,53.732 86.498,52.44 ccw(c87.394,53.34) 87.392,52.07 P4.2 P4.1
V_LOAD: C19.2 J1.1 P1.1 P1.2 R11.1 R23.1 U2.9 U3.7 | length 31
  Top Layer w0.254: U2.9 26.954,25.646 cw(c26.954,25.392) 27.133,25.572 28.321,24.384 R11.1
  Top Layer w0.508: P1.1 P1.2 ; C19.2 41.917,13.64 42.416,14.138 42.416,14.196 42.824,14.605 U3.7 ; v1(53.086,11.684) 54.737,11.684 ccw(c54.737,12.192) 55.245,12.192 R23.1
  Bottom Layer w0.508: P1.1 51.733,9.652 ccw(c51.733,10.16) 52.037,9.754 ccw(c51.733,10.16) 52.091,9.8 52.938,10.647 ccw(c52.578,11.005) 53.086,11.005 v1(53.086,11.684)
V_O_FUSE: F1.2 R11.2 U2.8 U2.10 | length 9.4
  Top Layer w0.254: U2.8 23.513,25.149 23.114,25.149 cw(c23.114,25.403) 22.86,25.403 22.86,25.867 cw(c23.114,25.867) 23.108,26.121 23.59,26.133 U2.10 26.93,26.146 ccw(c26.93,26.4) 27.082,26.197 ccw(c26.93,26.4) 27.109,26.22 28.247,27.358 ccw(c28.067,27.537) 28.27,27.385 ccw(c28.067,27.537) 28.321,27.537 R11.2
V_OUT: C7.1 C8.1 C11.2 F1.1 H2.1 P5.1 P5.3 R6.1 R7.1 R10.1 TP1.1 | length 12
  Top Layer w0.508: R7.1 53.713,34.342 53.808,34.313 ccw(c53.958,34.798) 53.958,34.29 61.343,34.29 cw(c61.341,33.782) 61.849,33.782 61.849,33.768 R6.1
  Top Layer w0.635: R10.1 C11.2
WDT_PWM: J_S2.1
WDT_RESET: J_S2.3 R18.2 U2.3 | length 15.6
  Top Layer w0.254: v1(13.716,26.416) 14.986,25.146 18.542,25.146 ; R18.2 18.915,28.321 18.542,27.948 18.542,25.146 ; U2.3 18.542,25.146
  Bottom Layer w0.254: J_S2.3 12.446,27.686 v1(13.716,26.416)
pads on no net: LED1.2 VIT1.1 VIT2.1 VIT3.1 VIT4.1

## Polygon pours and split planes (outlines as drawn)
WDT_RESET on Top Layer "NONET_L01_P-001" (solid, pour order 35): 17.399,25.019 17.399,25.273 17.6,25.273 ccw(c17.6,26.013) 18.124,25.49 18.307,25.673 ccw(c18.046,25.934) 18.415,25.934 18.415,26.547 18.669,26.547 18.669,25.654 19.05,25.273 19.558,25.273 19.558,25.019
V_O_FUSE on Top Layer "NONET_L01_P-001" (solid, pour order 34): 33.02,31.115 33.02,26.416 30.988,26.416 26.416,26.416 26.416,31.115
V_OUT on Top Layer "NONET_L01_P-001" (solid, pour order 9): 72.142,36.836 ccw(c70.012,38.967) 73.025,38.967 73.025,62.484 77.851,62.484 77.851,35.11 cw(c70.046,35.11) 75.565,29.591 cw(c69.74,35.416) 69.739,27.178 59.773,27.178 ccw(c59.773,23.298) 57.029,26.041 55.985,24.997 cw(c53.892,27.091) 53.034,24.257 34.417,24.257 34.417,31.115 35.477,31.115 cw(c35.477,26.315) 38.871,29.709 40.265,28.315 ccw(c42.703,30.752) 42.703,27.305 50.673,27.305 ccw(c50.673,28.956) 52.324,28.956 52.324,33.02 58.674,33.02 ccw(c58.674,33.528) 59.182,33.528 ccw(c58.674,33.528) 58.674,34.036 57.912,34.036 57.912,34.544 58.674,34.544 ccw(c58.674,35.052) 59.182,35.052 cw(c59.436,35.052) 59.436,35.306 68.448,35.306 ccw(c68.448,40.531)
V_LOAD on Top Layer "NONET_L01_P-001" (solid, pour order 19): 24.892,21.463 24.892,16.51 26.924,16.51 26.924,14.732 ccw(c29.591,14.732) 29.591,12.065 43.18,12.065 43.18,14.859 37.124,14.859 cw(c37.124,21.7) 32.286,16.863 31.564,17.585 cw(c33.874,19.895) 30.607,19.895 30.607,23.241 26.67,23.241 ccw(c26.67,21.463)
5V_LDO on Top Layer "NONET_L01_P-001" (solid, pour order 17): 10.541,15.367 8.255,15.367 8.255,14.097 10.414,14.097 cw(c10.414,12.827) 11.684,12.827 11.684,1.778 18.288,1.778 18.288,13.716 26.162,13.716 26.162,16.002 18.288,16.002 18.288,18.288 16.212,18.288 ccw(c16.212,14.407) 13.468,17.151 12.492,16.175 cw(c10.541,18.126)
GND on Top Layer "NONET_L01_P-001" (solid, pour order 18): 26.162,7.366 31.877,7.366 31.877,1.778 22.86,1.778 22.86,4.572 21.971,5.461 19.05,5.461 19.05,12.954 26.162,12.954
NetC21_2 on Top Layer "NONET_L01_P-001" (solid, pour order 33): 22.86,20.955 21.082,20.955 21.082,18.288 19.177,18.288 19.177,16.51 24.384,16.51 24.384,19.431 ccw(c22.86,19.431)
3V3 on Top Layer "NONET_L01_P-001" (solid, pour order 14): 76.596,17.541 77.163,18.108 cw(c77.904,17.368) 77.904,18.415 79.375,18.415 ccw(c79.375,20.701) 81.661,20.701 81.661,26.924 80.391,26.924 80.391,25.812 cw(c77.251,25.812) 79.471,23.591 78.644,22.764 cw(c75.81,25.598) 75.81,21.59 71.628,21.59 71.628,11.176 70.104,9.652 66.548,9.652 65.786,10.414 64.008,10.414 64.008,8.128 65.755,8.128 cw(c65.755,7.441) 66.241,7.927 ccw(c66.982,8.667) 66.982,7.62 69.596,7.62 cw(c69.596,6.394) 70.463,7.261 71.089,6.635 ccw(c72.39,7.936) 72.39,6.096 75.946,6.096 75.946,15.971 cw(c78.167,15.971)
NetC15_1 on Top Layer "NONET_L01_P-001" (solid, pour order 4): 42.38,35.903 42.202,35.725 cw(c41.068,34.591) 42.672,34.591 42.672,33.327 cw(c41.932,33.327) 42.455,32.803 42.037,32.385 40.64,32.385 40.64,30.988 47.498,30.988 47.498,33.528 45.06,33.528 cw(c45.06,34.138) 44.45,34.138 44.45,34.722 ccw(c43.667,34.722) 43.667,35.505 43.34,35.505 cw(c43.34,36.863)
NetC25_2 on Top Layer "NONET_L01_P-001" (solid, pour order 32): 70.104,6.477 70.216,6.365 cw(c68.952,5.102) 70.739,5.102 70.739,4.064 cw(c69.977,4.064) 69.977,3.302 65.024,3.302 cw(c65.024,3.937) 64.389,3.937 64.389,5.334 65.913,5.334 66.675,6.096 66.675,7.112 68.571,7.112 cw(c68.571,4.944)
5V_PS on Top Layer "NONET_L01_P-001" (solid, pour order 16): 60.118,6.61 63.23,3.497 ccw(c64.621,4.889) 64.621,2.921 74.925,2.921 ccw(c74.925,10.292) 80.137,5.08 80.834,5.777 ccw(c74.544,12.067) 83.439,12.067 83.439,22.733 84.709,22.733 84.709,6.53 cw(c81.209,6.53) 83.684,4.055 82.804,3.175 cw(c79.125,6.854) 79.125,1.651 61.192,1.651 cw(c61.192,3.745) 59.712,2.264 59.414,2.562 ccw(c57.627,0.775) 57.627,3.302 53.086,3.302 53.086,10.795 56.642,10.795 56.642,14.732 58.674,14.732 58.674,10.095 ccw(c63.603,10.095)
5V_PS on Top Layer "NONET_L01_P-001" (solid, remove dead copper, pour order 22): 84.709,23.718 84.709,22.733 83.439,22.733 83.439,26.819 cw(c85.533,26.819) 84.052,28.299 86.106,30.353 88.138,30.353 88.138,26.819 87.534,26.819 ccw(c87.534,24.344) 85.784,26.094 85.629,25.939 ccw(c87.849,23.718)
V_IN on Top Layer "NONET_L01_P-001" (solid, pour order 27): 41.91,62.611 34.036,62.611 34.036,61.341 35.582,61.341 cw(c35.582,59.861) 36.629,60.907 37.053,60.483 cw(c34.526,57.956) 38.1,57.956 38.1,54.61 41.91,54.61
V_IN on Top Layer "NONET_L01_P-001" (solid, pour order 0): 30.607,61.341 33.02,61.341 33.02,62.611 24.892,62.611 24.892,59.944 23.25,58.302 cw(c18.629,62.923) 18.629,56.388 13.97,56.388 13.97,51.054 27.686,51.054 27.686,53.743 cw(c29.166,53.743) 28.12,54.79 29.105,55.775 ccw(c27.624,57.255) 29.718,57.255 29.718,60.452 cw(c30.607,60.452)
PH on Top Layer "NONET_L01_P-001" (solid, pour order 5): 54.895,46.767 55.595,47.467 cw(c58.122,44.94) 58.376,48.505 58.376,62.484 52.324,62.484 52.324,52.578 50.546,50.8 44.928,50.8 44.928,50.038 42.418,50.038 42.418,45.466 42.164,45.212 41.656,45.212 41.656,43.434 43.732,43.434 ccw(c43.732,46.395) 45.825,44.301 46.631,45.107 cw(c48.111,43.627) 48.111,45.72 52.368,45.72 ccw(c52.368,49.294)
GND on Top Layer "NONET_L01_P-001" (solid, pour order 26): 58.376,46.99 58.376,36.576 53.086,36.576 52.832,36.83 52.832,40.386 54.356,41.91 54.356,42.97 cw(c57.93,42.97) 55.403,45.497 55.849,45.943 cw(c58.376,43.416)
GND on Top Layer "NONET_L01_P-001" (solid, pour order 29): 51.308,54.168 51.308,51.374 46.736,51.374 46.736,54.168
NetC4_2 on Top Layer "NONET_L01_P-001" (solid, pour order 28): 43.688,62.484 51.054,62.484 51.054,54.61 43.688,54.61
GND on Top Layer "NONET_L01_P-001" (solid, pour order 11): 28.702,51.054 28.702,52.114 cw(c32.276,52.114) 29.749,54.641 30.099,54.991 ccw(c27.953,57.137) 30.988,57.137 30.988,59.69 cw(c32.004,59.69) 32.004,60.706 33.02,60.706 cw(c33.02,58.928) 34.798,58.928 34.798,51.054
SRP on Top Layer "NONET_L01_P-001" (solid, pour order 25): 59.69,38.1 59.69,62.484 70.612,62.484 70.612,40.255 cw(c68.457,40.255) 68.457,38.1
5V_LDO on Top Layer "NONET_L01_P-001" (solid, pour order 24): 9.398,31.242 9.398,29.337 7.62,29.337 6.985,28.702 6.985,27.051 5.216,27.051 ccw(c5.216,25.496) 4.117,26.596 ccw(c5.163,25.549) 3.683,25.549 3.683,23.368 2.54,23.368 2.413,23.241 2.413,25.496 cw(c5.247,25.496) 3.243,27.5 6.985,31.242
3V3 on Top Layer "NONET_L01_P-001" (solid, pour order 23): 87.433,36.322 ccw(c87.433,34.039) 85.818,35.653 81.311,31.146 ccw(c83.531,28.925) 80.391,28.925 80.391,26.924 81.661,26.924 cw(c85.647,26.924) 82.828,29.742 84.08,30.994 cw(c87.131,27.944) 87.131,32.258 ccw(c87.131,33.265) 88.138,33.265 88.138,35.617 ccw(c87.433,35.617)
GND on Top Layer "NONET_L01_P-001" (solid, pour order 15): 56.134,14.351 56.134,15.494 59.69,15.494 59.69,12.7 ccw(c61.722,12.7) 60.738,10.922 66.04,10.922 66.802,10.16 69.342,10.16 70.866,11.684 70.866,17.78 67.818,17.78 66.548,19.05 66.548,26.035 58.801,26.035 58.801,19.177 54.102,19.177 54.102,14.351
NetC1_1 on Top Layer "NONET_L01_P-001" (solid, pour order 13): 16.51,46.228 16.51,50.292 12.192,50.292 12.192,47.244 14.732,47.244 14.732,46.228
V_IN on Top Layer "NONET_L01_P-001" (solid, pour order 12): 21.082,41.402 21.082,44.196 13.208,44.196 13.208,41.402
V_IN_MOS on Top Layer "NONET_L01_P-001" (solid, pour order 10): 26.797,45.847 ccw(c26.797,47.244) 28.194,47.244 28.194,50.292 33.826,50.292 ccw(c33.826,53.253) 35.919,51.159 cw(c38.118,48.961) 38.118,52.07 41.91,52.07 41.91,46.482 cw(c41.148,46.482) 41.148,45.72 40.07,45.72 ccw(c40.07,40.35) 36.273,44.147 35.152,43.026 cw(c31.232,46.946) 31.231,41.402 24.384,41.402 24.384,44.704 16.764,44.704 16.764,50.292 25.4,50.292 25.4,47.244 ccw(c26.797,47.244)
MPPSET on Top Layer "NONET_L01_P-001" (solid, pour order 8): 22.606,38.354 22.203,38.354 ccw(c22.203,36.874) 20.724,36.83 16.256,36.83 16.256,40.894 20.828,40.894 21.082,40.64 21.082,39.779 ccw(c21.904,39.779) 21.54,39.041 ccw(c22.308,40.596) 22.308,38.862 22.606,38.862 21.59,38.862 22.606,38.862
NetC16_2 on Top Layer "NONET_L01_P-001" (solid, pour order 2): 47.603,13.059 ccw(c49.083,11.579) 46.99,11.579 46.99,9.144 43.688,9.144 43.688,3.302 51.816,3.302 51.816,12.446 ccw(c50.546,12.446) 50.546,13.716 49.189,13.716 ccw(c49.189,11.474)
GND on Top Layer "NONET_L01_P-001" (solid, pour order 1): 46.736,23.495 46.736,18.034 48.26,16.51 48.26,13.716 45.72,13.716 45.72,16.51 43.18,16.51 42.672,17.018 37.973,17.018 37.973,23.495
no net on Bottom Solder "NONET_L01_P-001" (solid): 43.942,18.32 43.942,11.398 49.784,11.398 49.784,18.32
no net on Bottom Solder "NONET_L01_P-001" (solid, pour order 6): 34.036,54.356 34.036,34.544 52.578,34.544 52.578,54.356
GND on Bottom Layer "NONET_L01_P-001" (solid, remove dead copper, pour order 30): 0,0 94.361,0 94.361,63.627 0,63.627

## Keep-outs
Keep-Out Layer:
  lines w0.5: 0,0 94.361,0 ; 0,0 0,63.754 ; 0,0 0,63.754 ; 0,63.754 94.361,63.754 ; 0,63.754 94.361,63.754 ; 94.361,0 94.361,63.754 ; 94.361,0 94.361,63.754

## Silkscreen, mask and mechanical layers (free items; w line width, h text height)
Top Overlay:
  drawing of 41 lines, arcs and shapes, not listed
  text "+" at 26.924,54.864 h1.52
  text "-" at 32.004,54.864 h1.52
  text "+" at 74.93,54.864 h1.52
  text "-" at 80.01,54.864 h1.52
  text "Design by LDH /   29012026" at 73.406,51.562 h0.64 r180
  text "Ver5.0.1" at 73.406,50.305 h1.4 r180
  text "POWER MODULE" at 84.177,50.294 h1.4 r180
  text "IN-" at 37.592,24.13 h1.27 r180
  text "OUT+" at 62.23,24.13 h1.27 r180
  text "IN+" at 37.592,10.414 h1.27 r180
  text "OUT+" at 62.23,10.414 h1.27 r180
Bottom Overlay:
  text "VIN" at 28.829,56.134 h1.02 r180
  text "VOUT" at 76.243,56.134 h1.02 r180
  text "VIN" at 83.313,52.578 h1.02 r180
  text "DCIN" at 14.479,52.07 h1.02 r180
  text "-5V" at 83.144,50.038 h1.02 r180
  text "GND" at 83.144,47.498 h1.02 r180
  text "GND" at 2.668,35.611 h0.76 r180
  text "SDA" at 10.439,35.611 h0.76 r180
  text "3V3" at 83.744,35.611 h0.76 r180
  text "GND" at 91.008,35.611 h0.76 r180
  text "GND" at 2.668,33.071 h0.76 r180
  text "SCL" at 10.439,33.071 h0.76 r180
  text "3V3" at 83.744,33.071 h0.76 r180
  text "GND" at 91.008,33.071 h0.76 r180
  text "GND" at 91.008,30.531 h0.76 r180
  text "+5V_L" at 1.144,30.404 h0.76 r180
  text "+5V_L" at 10.439,30.404 h0.76 r180
  text "+5V_S" at 82.221,30.404 h0.76 r180
  text "BATT+" at 72.603,28.829 h1.02 r180
  text "RST" at 10.439,27.991 h0.76 r180
  text "GND" at 91.008,27.991 h0.76 r180
  text "+5V_L" at 1.144,27.864 h0.76 r180
  text "+5V_S" at 82.221,27.864 h0.76 r180
  text "BATT-" at 72.603,26.289 h1.02 r180
  text "3V3" at 2.668,25.451 h0.76 r180
  text "PWM" at 10.439,25.451 h0.76 r180
  text "-5V" at 83.744,25.451 h0.76 r180
  text "GND" at 91.008,25.451 h0.76 r180
Bottom Solder:
  pour cut-out: 44.577,53.34 44.577,44.45 42.799,42.672 39.878,42.672 39.878,44.45 39.37,44.958 38.989,44.958 38.481,44.45 38.481,41.148 45.72,41.148 47.498,42.926 45.847,44.577 45.847,53.34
